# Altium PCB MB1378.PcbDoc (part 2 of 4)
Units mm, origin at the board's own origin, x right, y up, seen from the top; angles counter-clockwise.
Board outline 54.22 x 80.1 mm, 4 copper layers (Top Layer, L2-GND, L3, Bottom Layer), stack 0.771 mm thick; 206 components, 159 nets, 727 pads, 330 vias.
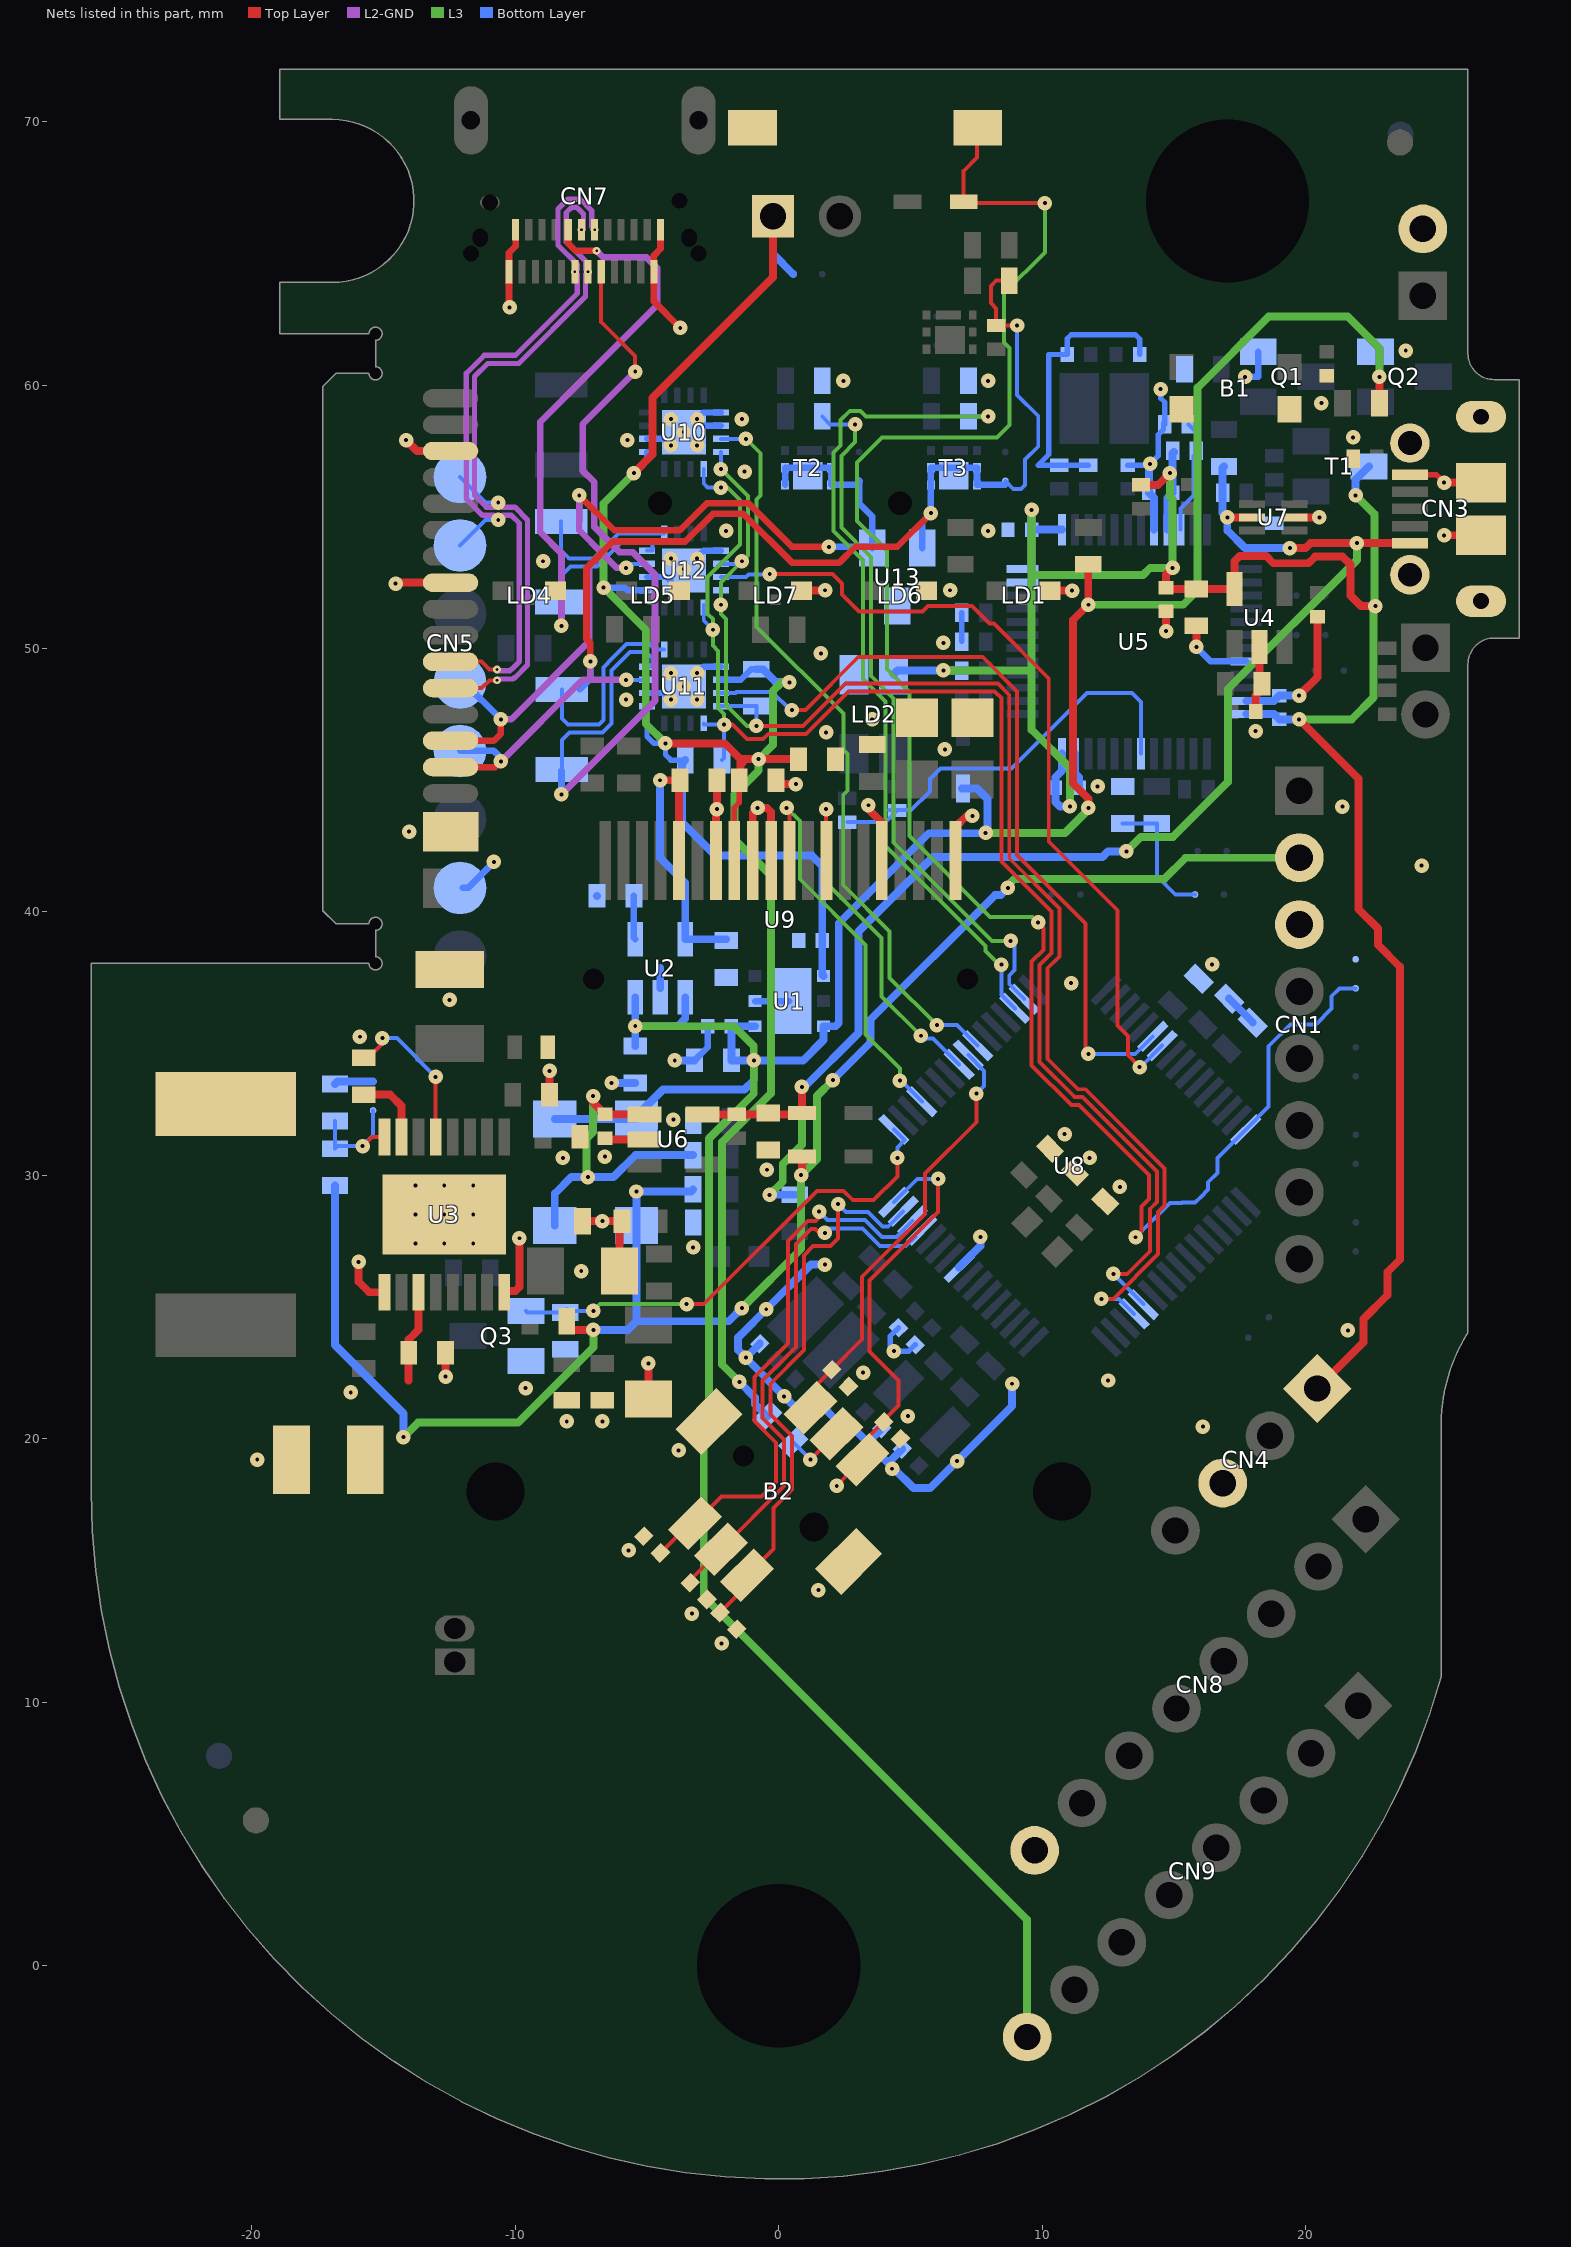
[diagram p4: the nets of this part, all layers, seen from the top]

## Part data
B1: library part MCD-01510, "Microminiature SMT Top, 2N, N.O., IP67", Manufacturer=C&K, Manufacturer_Part_Number="KMR721NG LFS", Package=KMR7
B2: library part MCD-00132, "Joystick, 4 dir, 1 OK", Manufacturer="XIEJIA Electronics", Manufacturer_Part_Number=MT-008A
C1 C3 C5 C11 C34 C35 C37 C38: library part MCD-00010, "Capacitor, MLCC, 1uF, 16V, X5R, 10%, 0603, T=0,8mm", Manufacturer=YAGEO, Manufacturer_Part_Number=CC0603KRX5R7BB105, Package=C0603
C2 C4 C44 C45 C46 C50 C51 C52 C53 C54: library part MCD-00102, "Capacitor, MLCC, 100nF, 16V, X7R, 10%, 0402, T=0,5mm", Manufacturer=YAGEO, Manufacturer_Part_Number=CC0402KRX7R7BB104, Package=C0402
C6 C49: library part MCD-01007, "Capacitor, MLCC, 10nF, 16V, X7R, 10%, 0603, T=0.8mm", Manufacturer=YAGEO, Manufacturer_Part_Number=CC0603KRX7R7BB103, Package=C0603
C7: library part MCD-00551, "Capacitor, MLCC, 2.2uF, 10V, X5R, 10%, 0603, T=0,8mm", Alternate_Manufacturer=YAGEO, Alternate_Manufacturer_Part_Number=CC0603KRX5R6BB225, Manufacturer=KEMET, Manufacturer_Part_Number=C0603C225K8PACTU, Package=C0603
C8 C9: library part MCD-01050, "Capacitor, X7R, 68nF, 50V, 10%, 0603, T=1mm", Manufacturer=AVX, Manufacturer_Part_Number=06035C683KAT2A, Package=C0603
C10 C18: library part MCD-01048, "Capacitor, NP0, 47pF, 50V, C0G, 5%, 1206, T=1.25mm", Manufacturer=AVX, Manufacturer_Part_Number=06035A470JAT4A, Package=C1206_H1P25
C12: library part MCD-00614, "Capacitor, MLCC, 22uF, 16V, 1210, X7R, 20%, T=2,5mm, ESR 2mohm@410KHz", Manufacturer=MURATA, Manufacturer_Part_Number=GCM32ER71C226ME19, Package=C1210
C13: library part MCD-01056, "Capacitor, X7R, 10µF, 50V, 20%, 1210, T=2.5mm", Manufacturer=TDK, Manufacturer_Part_Number=C3225X7R1H106M250AC, Package=C1210
C14: library part MCD-01053, "Capacitor, C-series, X5R, 1µF, 50V, 10%, 0603, T=0.8mm", Manufacturer=TDK, Manufacturer_Part_Number=C1608X5R1H105K080AB, Package=C0603
C15: library part MCD-01052, "Capacitor, X7R, 33nF, 50V, 5%, 0603, T=1.25mm", Manufacturer=AVX, Manufacturer_Part_Number=06035C333JAT2A, Package=C0603
C16: library part MCD-00009, "Capacitor, MLCC, 4.7uF, 16V, X5R, 10%, 0603, T=0.8mm", Manufacturer=YAGEO, Manufacturer_Part_Number=CC0603KRX5R7BB475, Package=C0603
C17: library part MCD-01049, "Capacitor, MLCC, 4.7nF, 100V, X7R, 10%, 0603, T=1mm", Manufacturer=AVX, Manufacturer_Part_Number=06031C472K4T2A, Package=C0603
C19 C20: library part MCD-00015, "Capacitor, MLCC, 10pF, 50V, NPO, 5%, 0402, T=0,5mm", Manufacturer=YAGEO, Manufacturer_Part_Number=CC0402JRNPO9BN100, Package=C0402
C21 C23 C32 C48: library part MCD-00238, "Capacitor, MLCC, 1uF, 6V3, X5R, 10%, 0603, T=0,8mm", Manufacturer=YAGEO, Manufacturer_Part_Number=CC0603KRX5R5BB105, Package=C0603
C22 C24 C26 C28 C29 C30 C31 C33: library part MCD-00006, "Capacitor, MLCC, 100nF, 16V, X7R, 10%, 0402, T=0.5mm", Manufacturer=YAGEO, Manufacturer_Part_Number=CC0402KRX7R7BB104, Package=C0402
C25: library part MCD-00011, "Capacitor, MLCC, 10nF, 16V, X7R, 10%, 0402, T=0.5mm", Manufacturer=YAGEO, Manufacturer_Part_Number=CC0402KRX7R7BB103, Package=C0402
C27: library part MCD-00638, "Capacitor, MLCC, 20pF, 50V, NPO, 5%, 0603, T=0,8mm", Manufacturer=YAGEO, Manufacturer_Part_Number=CC0603JRNPO9BN200, Package=C0603
C36 C41: library part MCD-01043, "Capacitor, Tantalum, 4.7µF, 25V, 10%, 1206", Manufacturer=VISHAY, Manufacturer_Part_Number=293D475X9025A2TE3, Package=CPOL_TAJ-A_1206_H180
C39 C40: library part MCD-01374, "Capacitor, MLCC, 5.6pF, 50V, NPO, 5%, 0402, T=0,5mm", Manufacturer=YAGEO, Manufacturer_Part_Number=CC0402BRNPO9BN5R6, Package=C0402
C42 C43: library part MCD-00556, "Capacitor, MLCC, 3.9pF, 50V, NPO, +-0.25pF, 0402, T=0,5mm", Manufacturer=YAGEO, Manufacturer_Part_Number=CC0402CRNPO9BN3R9, Package=C0402
C47: library part MCD-00097, "Capacitor, MLCC, 4.7uF, 16V, X5R, 20%, 0603, T=0,8mm", Manufacturer=MURATA, Manufacturer_Part_Number=GRM188R61C475MAAJ, Package=C0603
CC1 CC2 D+ D- GND SBU1 SBU2 VBUS: library part MCD-00177, "Test Point 2mm", Manufacturer=n/a
CN1: library part MCD-01382, "Header, 8x1, 2.54mm, RA, through-hole", Manufacturer=SAMTECH, Manufacturer_Part_Number=TSW_108_08_G_S_RA
CN2 JP1: library part MCD-00032, "Header, 2x1, 2,54mm, VR, TH, Height 5.84mm/2.54mm", Manufacturer=SAMTEC, Manufacturer_Part_Number=TSW-102-07-x-S
CN3: library part MCD-00028, "USB-MICRO-B, 0.65mm, RA, SMT, Bottom Mount,", Manufacturer=MOLEX, Manufacturer_Part_Number=1050170001
CN4: library part MCD-00029, "Header, 4x1, 2,54mm, VR, TH, Height 5.84mm/2.54mm", Manufacturer=SAMTEC, Manufacturer_Part_Number=TSW-104-07-x-S
CN5: library part MCD-01383, "Connector, USB TYpe-C Plug cable interface to PCB with specific layout", Manufacturer="ADVANCED-CONNECTEK (KSN) INC.", Manufacturer_Part_Number="TBD (custom-made connector)", Package="USB Type-C Pug captive cable"
CN6: library part MCD-00314, "Header, 2x1, 2.54mm, VR, TH, Height 6mm/3mm", Manufacturer=JIUBABA, Manufacturer_Part_Number=PHFS25-11-02-G0B115-T-1
CN7: library part MCD-01022, "USB Type-C connector DX07 Series RECEPTACLE", Manufacturer=JAE, Manufacturer_Part_Number=DX07S024JJ2, Package="2x24 pin"
CN8 CN9: library part MCD-00239, "Header, 8x1, 2,54mm, VR, TH, Height 5.84mm/2.54mm", Manufacturer=SAMTEC, Manufacturer_Part_Number=TSW-108-07-x-S
D1 D2: library part MCD-01059, "LOW DROP POWER SCHOTTKY RECTIFIER 1A 30V VF=0.3V", Manufacturer=STMICROELECTRONICS, Manufacturer_Part_Number=STPS1L30A, Package=DIO_SMA_1A_2K
D3 D4 D5 D6: library part MCD-00034, "BAT60JFILM", Manufacturer=STMICROELECTRONICS
HW1: library part MCD-00628, "\"ROHS\" logo footprint for PCB"
HW2: library part MCD-00627, "\"Hand\" ESD logo footprint for PCB"
HW4: library part MCD-00625, "\"STMicroelectronics\" logo footprint for PCB"
JP2: library part MCD-01428, "Header, 2x1, 1,27mm, Right Angled, Single Row, Height 3.05mm/1.27mm", Manufacturer="W & P Products", Manufacturer_Part_Number=707-2-02-2-20-00
L1: library part MCD-01372, "Inductor 6.8µH +/-20% Isat= 13.5A DCR=33.40 mOhm", Manufacturer="WURTH ELEKTRONIK", Manufacturer_Part_Number="744 373 580 68", Package=WE-LHMI_SMD_8040
L2: library part MCD-00552, "Bead,600R,350mA,0603", Manufacturer=TAI-TECH, Manufacturer_Part_Number=FCM1608KF-601T03
LD1 LD6 LD7: library part MCD-01376, "LED GREEN, 2.2V, 20mA, side", Manufacturer="BROADCOM LIMITED", Manufacturer_Part_Number=HSMG-C120, Package=HSM-C120
LD2: library part MCD-00051, "LED Bicolor", Alternate_Manufacturer=EVERLUCK, Alternate_Manufacturer_Part_Number=LE-RGW35280, Manufacturer="AVAGO TECHNOLOGIES", Manufacturer_Part_Number=HSMF-A201-A00J1
LD3: library part MCD-00587, "LED Red, 0603 SMD, 2V Forward Voltage", Alternate_Manufacturer="OSRAM OPTO SEMICONDUCTORS", Alternate_Manufacturer_Part_Number="LS Q976-NR-1", Manufacturer=VISHAY, Manufacturer_Part_Number=VLMS1300-GS08, Package="LED 0603"
LD4 LD5: library part MCD-01378, "LED ORANGE, 1.9V, 20mA, side", Manufacturer="BROADCOM LIMITED", Manufacturer_Part_Number=HSML-C120
Q1 Q2: library part MCD-01385, "Transistor Bipolar NPN, 45V, 500mA, 100MHz, 300mW, SOT23-3", Manufacturer="ON SEMICONDUCTOR", Manufacturer_Part_Number=BC817-25LT3G, Package=SOT23-3
Q3: library part MCD-01518, "MOSFET, Single N-Channel , Vgs(th): 2.5V, Id: 280mA, Vds(max): 60V, Vgs(max): +/-20V, Rdson:3 ohm@Vgs=5V", Alternate_Manufacturer=FAIRCHILD, Alternate_Manufacturer_Part_Number=NDS7002A, Manufacturer="ON SEMICONDUCTOR", Package=SOT23-3L
R1 R2 R8: library part MCD-00220, "Resistor,10K,0603,1%,1/10W", Manufacturer=YAGEO, Manufacturer_Part_Number=RC0603FR-0710KL, Package=R0603
R3 R32 R33 R52 R61: library part MCD-00354, "Resistor,470R,0603,1%,1/10W", Manufacturer=YAGEO, Manufacturer_Part_Number=RC0603FR-07470RL, Package=R0603
R4 R5 R7: library part MCD-00341, "Resistor,15K,0603,1%,1/10W", Manufacturer=YAGEO, Manufacturer_Part_Number=RC0603FR-0715KL, Package=R0603
R6: library part MCD-00426, "Resistor,2M,0603,1%,1/10W", Manufacturer=YAGEO, Manufacturer_Part_Number=RC0603FR-072ML, Package=R0603
R9: library part MCD-00478, "Resistor,43K,0603,1%,1/10W", Manufacturer=YAGEO, Manufacturer_Part_Number=RC0603FR-0743KL, Package=R0603
R10: library part MCD-01032, "Resistor 499K 1% 75V 0.063W", Manufacturer=MULTICOMP, Manufacturer_Part_Number=MC0603SAF4993T5E, Package=R0603
R11 R20 R21: library part MCD-00065, "Resistor,4K7,0402,1%,1/16W", Alternate_Manufacturer=YAGEO, Alternate_Manufacturer_Part_Number=RT0402FRE074K7L, Manufacturer_Part_Number=RC0402FR-074K7L, Package=R0402
R12: library part MCD-00055, "Resistor,2K7,0402,1%,1/16W", Manufacturer=YAGEO, Manufacturer_Part_Number=RC0402FR-072K7L, Package=R0402
R13 R22 R23: library part MCD-00052, "Resistor,0R,0402,5%,1/16W", Manufacturer=YAGEO, Manufacturer_Part_Number=RC0402JR-070RL, Package=R0402
R14 R17 R34: library part MCD-00059, "Resistor,100K,0402,1%,1/16W", Alternate_Manufacturer=YAGEO, Alternate_Manufacturer_Part_Number=RT0402FRE07100KL, Manufacturer_Part_Number=RC0402FR-07100KL, Package=R0402
R15 R16 R28 R30: library part MCD-00053, "Resistor,10K,0402,1%,1/16W", Manufacturer=YAGEO, Manufacturer_Part_Number=RC0402FR-0710KL, Package=R0402
R18 R45: library part MCD-00224, "Resistor,100R,0603,1%,1/10W", Manufacturer=YAGEO, Manufacturer_Part_Number=RC0603FR-07100RL, Package=R0603
R19 R25: library part MCD-00067, "Resistor,100R,0402,1%,1/16W", Manufacturer=YAGEO, Manufacturer_Part_Number=RC0402FR-07100RL, Package=R0402
R24 R26: library part MCD-00062, "Resistor,330R,0402,1%,1/16W", Manufacturer=YAGEO, Manufacturer_Part_Number=RC0402FR-07330RL, Package=R0402
R27: library part MCD-00069, "Resistor,36K,0402,1%,1/16W", Manufacturer=YAGEO, Manufacturer_Part_Number=RC0402FR-0736KL, Package=R0402
R29: library part MCD-00068, "Resistor,1K5,0402,1%,1/16W", Manufacturer=YAGEO, Manufacturer_Part_Number=RC0402FR-071K5L, Package=R0402
R31: library part MCD-00508, "Resistor,680R,0603,1%,1/10W", Manufacturer=YAGEO, Manufacturer_Part_Number=RC0603FR-07680RL, Package=R0603
R35 R36 R38 R39 R41 R44 R57 R58 R62: library part MCD-00056, "Resistor,0R,0603,5%,1/10W", Manufacturer=YAGEO, Manufacturer_Part_Number=RC0603JR-070RL, Package=R0603
R37 R42 R51 R59 R60: library part MCD-00223, "Resistor,100K,0603,1%,1/10W", Manufacturer=YAGEO, Manufacturer_Part_Number=RC0603FR-07100KL, Package=R0603
R40: library part MCD-00506, "Resistor,620K,0603,1%,1/10W", Manufacturer=YAGEO, Manufacturer_Part_Number=RC0603FR-07620KL, Package=R0603
R43 R54: library part MCD-00430, "Resistor,22K,0603,1%,1/10W", Manufacturer=YAGEO, Manufacturer_Part_Number=RC0603FR-0722KL, Package=R0603
R46 R47: library part MCD-00070, "Resistor,1K,0603,1%,1/10W", Manufacturer=YAGEO, Manufacturer_Part_Number=RC0603FR-071KL, Package=R0603
R48 R49 R50: library part MCD-01029, "0.015 Ohm 1W 1% 1206 Shunt resistor for current sensing", Manufacturer=PANASONIC, Manufacturer_Part_Number=ERJ8CWFR015V, Package=1206
R53: library part MCD-00259, "Resistor,33K,0603,1%,1/10W", Manufacturer=YAGEO, Manufacturer_Part_Number=RC0603FR-0733KL, Package=R0603
R55: library part MCD-00257, "Resistor,1M,0603,1%,1/10W", Manufacturer=YAGEO, Manufacturer_Part_Number=RC0603FR-071ML, Package=R0603
R56: library part MCD-00333, "Resistor,5K1,0402,1%,1/16W", Manufacturer=YAGEO, Manufacturer_Part_Number=RC0402FR-075K1L, Package=R0402
R63: library part MCD-00222, "Resistor,47K,0603,1%,1/10W", Manufacturer=YAGEO, Manufacturer_Part_Number=RC0603FR-0747KL, Package=R0603
SB1 SB2 SB3 SB4 SB5 SB6 SB9: library part MCD-00071, "Solder Bridge ON"
SB7 SB8 SB10 SB11 SB12 SB13 SB14 SB15: library part MCD-00072, "Solder Bridge OFF"
SB16: library part MCD-00072, "Solder Bridge OFF", Manufacturer=YAGEO, Manufacturer_Part_Number=RC0603JR-070RL, Package=SB0603
SW1: library part MCD-01373, "Reed switch, CT05 series, SPST-NO, CMS, 500mA, 140Vdc, 5W", Manufacturer="COTO TECHNOLOGY", Manufacturer_Part_Number=CT05-G1, Package=CT05
T1: library part MCD-00073, "NPN Bipolar Transistor", Manufacturer=NXP, Manufacturer_Part_Number=BSR14
T2 T3 T5: library part MCD-01028, "N-channel 20 V, 0.025 O typ., 6 A STripFET™ V Power MOSFET in a PowerFLAT™ 2x2 package", Manufacturer=STMICROELECTRONICS, Manufacturer_Part_Number=STL6N2VH5, Package="PowerFLAT 2x2"
TARGET1 TARGET2 TARGET3 TARGET4: library part MIRE, "MIRE"
U1: library part MCD-00215, "Low quiescent current and low noise voltage regulators", Manufacturer=STMICROELECTRONICS, Manufacturer_Part_Number=LD39050PU33R
U2: library part MCD-01030, "LDO VOLTAGE REGULATOR, 3.6V, 150mA, 5-SOT-23, FULL REEL", Manufacturer="TEXAS INSTRUMENTS", Package=REG_SOT23-5L
U3: library part MCD-01016, "Integrated Circuit 40V, 1A Synchronous Buck-Boost DC/DC Converter with Programmable Output Current", Manufacturer="LINEAR TECHNOLOGY", Manufacturer_Part_Number=LTC3114-1, Package="16-Lead Plastic TSSOP + exposed pad"
U4: library part MCD-00086, "Ultra low drop-low noise BiCMOS voltage, regulators low ESR capacitors compatible", Manufacturer=STMICROELECTRONICS, Manufacturer_Part_Number=LD3985M33R
U5: library part MCD-00085, "Medium-density performance line ARM-based 32-bit MCU with 128KB Flash", Manufacturer=STMICROELECTRONICS, Manufacturer_Part_Number=STM32F103CBT6
U6: library part MCD-00083, "Enhanced single channel power switches with active low enable pin", Alternate_Manufacturer="TEXAS INSTRUMENTS", Alternate_Manufacturer_Part_Number=TPS2041C, Manufacturer=STMICROELECTRONICS
U7: library part MCD-00169, "USB OTG FS ESD protection", Manufacturer=STMICROELECTRONICS, Manufacturer_Part_Number=USBLC6-2P6
U8: library part MCD-01047, "ARM® Cortex®-M0+ 32-bit MCU, 128 KB Flash, 32 KB RAM, / 4x USART, timers, ADC, DAC, comm. I/F, 1.65-3.6V", Manufacturer=STMICROELECTRONICS, Manufacturer_Part_Number=STM32G071RBT6, Package=LQFP64
U9: library part MCD-01511, "128*64 20-pin OLED display driver SSD1306BZ Parallel or SPI interface", Manufacturer=RITDISPLAY, Manufacturer_Part_Number=9OL9935701000
U10 U11 U12: library part MCD-01017, "Texas Intruments High- or Low-Side Measurement, Bidirectional CURRENT/POWER MONITOR with I2C™ Interface", Manufacturer=TI, Manufacturer_Part_Number=INA230, Package=QFN16
U13: library part MCD-01027, "DUAL TRANSIL ARRAY FOR ESD PROTECTION", Manufacturer=STMICROELECTRONICS, Manufacturer_Part_Number=ESDA25L, Package=ESD_SOT23
U14: library part MCD-01207, "High power Transient voltage suppressor:25V/35A EOS and ESD transients protection.", Manufacturer=STMICROELECTRONICS, Manufacturer_Part_Number=ESDA25P35-1U1M, Package=QFN1610
X1 X3: library part MCD-00092, "Crystal 8Mhz, 8pF, -+50PPM, SMD", Manufacturer=NDK, Manufacturer_Part_Number="NX3225GD 8MHz EXS00A-CG04874"
X2: library part MCD-00091, "Crystal 32.768kHz, 6pF, -+20PPM, R=50K, SMD", Manufacturer=NDK, Manufacturer_Part_Number="NX3215SA 32.768KHz EXS00A-MU00525"

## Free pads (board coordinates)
  round 0.508 on Mech16: 1(79.747,-56.535) 1(85.97,-56.535)
  round 0.8 hole 2.2 unplated mask+0.8: H1(-10.756,17.999) H1(10.756,17.999)
  round 0.8 hole 6.2 unplated mask+2.8: H1(0,0) H1(17.035,66.99)
  round 0.5 hole 0.9 unplated: H2(-4.509,55.512) H2(4.603,55.512)

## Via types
v1: diameter 0.55, hole 0.15, Top Layer to Bottom Layer, 308 vias
v2: diameter 0.3, hole 0.1, Top Layer to L2-GND, 22 vias

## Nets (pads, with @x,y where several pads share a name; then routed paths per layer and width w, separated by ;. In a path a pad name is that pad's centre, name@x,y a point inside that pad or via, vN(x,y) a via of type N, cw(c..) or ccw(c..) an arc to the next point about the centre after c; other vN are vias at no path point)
3V3_LDO: C3.1 C4.2 C37.1 CN6.1 R45.1 R46.2 R47.2 SB6.1 U1.4 U9.8 U10.9 U11.2 U11.9 U12.9 | length 88.1
  Top Layer w0.2: U9.8@-1.687,41.949 -1.687,43.963 -1.5,44.15 C37.1@-1.5,45
  Top Layer w0.3: v1(-5.497,56.662) -4.797,57.362 -4.797,59.512 -0.217,64.092 CN6.1@-0.217,66.412 ; v1(-4.3,46.4) -2.051,46.4 -1.45,45.799 ; C37.1@-1.5,45 -1.45,45.05 -1.45,45.6 ; C3.1@0.75,45.799 v1(-0.761,45.799) -1.251,45.799 ; -1.45,45.6 -1.251,45.799 ; -1.45,45.6 -1.45,45.799 ; -1.45,45.799 -1.251,45.799
  L3 w0.3: v1@-5.522,56.637 -6.647,55.512 v1(-6.647,52.312) -5.047,50.712 -5.047,47.147 v1(-4.3,46.4) ; v1(-1.497,22.162) -2.147,22.812 -2.147,31.262 -0.297,33.112 -0.297,41.384 -1.675,42.761 -1.675,44.451 -0.761,45.365 v1(-0.761,45.799) -0.222,46.337 -0.222,48.387 0.103,48.712 v1(0.403,48.712)
  Bottom Layer w0.2: U11.9@-4.997,47.812 -4.997,46.664 -4.733,46.4 v1(-4.3,46.4) -4.3,45.967 -4.096,45.762 R46.2@-3.547,45.762
  Bottom Layer w0.24: v1(-6.647,52.312) -5.847,52.312 -5.747,52.212 U12.9@-4.997,52.212 ; v1(-5.497,56.662) -4.997,57.162 U10.9@-4.997,57.462 ; U11.2@-2.197,48.812 -1.447,48.812 -1.047,49.212 R47.2@-0.847,49.212
  Bottom Layer w0.3: R46.2@-3.547,45.762 -3.675,45.635 -3.675,43.41 -2.403,42.137 1.263,42.137 1.653,41.747 C4.2@1.653,38.912 1.653,37.612 U1.4@1.703,37.562 ; v1(-1.497,22.162) -0.897,21.562 -0.897,21.312 R45.1@-0.437,20.852 ; R47.2@-0.847,49.212 -0.597,49.212 -0.117,48.732 0.383,48.732 v1(0.403,48.712) ; CN6.1@-0.217,66.412 -0.217,64.982 SB6.1@0.553,64.212
3V3_STLK: C23.2 C24.2 C28.2 C29.2 C30.2 C31.2 CN4.1 LD2.4 R13.2 R17.2 R20.1 T1.3 U4.5 U5.1 U5.9 U5.24 U5.36 U5.48 | length 91.9
  Top Layer w0.3: R17.2@13.753,56.212 14.403,56.212 v1(14.853,56.662) ; v1(14.953,53.062) 14.703,52.812 C24.2@14.703,52.312 14.703,52.262 C23.2@15.853,52.262 U4.5@17.303,52.262 17.303,53.312 17.503,53.512 18.503,53.512 18.778,53.237 20.114,53.237 20.364,53.487 21.402,53.487 21.703,53.187 21.703,52.012 22.103,51.612 v1(22.653,51.612) ; v1(19.753,47.312) 22.003,45.062 22.003,40.112 22.745,39.37 22.745,38.755 23.578,37.922 23.578,26.801 23.103,26.326 23.103,25.449 22.203,24.549 22.203,23.662 CN4.1@20.447,21.906
  L3 w0.3: v1@6.143,49.172 v1(6.253,49.172) 9.603,49.172 ; v1(9.603,55.262) 9.603,52.787 ; v1(11.055,44.005) 11.055,45.46 9.603,46.912 9.603,49.172 ; v1(14.853,56.662) 14.853,55.762 14.953,55.662 v1(14.953,53.062) 14.103,53.062 13.828,52.787 9.603,52.787 ; v1(19.753,47.312) 21.753,47.312 22.578,48.137 22.578,51.537 v1(22.653,51.612) 22.613,51.652 22.613,55.102 v1(21.903,55.812) ; 9.603,49.172 9.603,52.787
  Bottom Layer w0.3: LD2.4@4.353,49.012 4.513,49.172 v1(6.253,49.172) R13.2@6.943,49.172 ; U5.48@9.603,53.062 C28.2@9.603,54.512 ; v1(9.603,55.262) C28.2@9.603,54.512 ; U5.36@10.753,46.012 10.753,45.362 10.503,45.112 C31.2@10.503,44.712 10.503,44.177 10.675,44.005 v1(11.055,44.005) ; U5.1@10.753,54.512 C28.2@9.603,54.512 ; U5.9@14.753,54.512 14.753,55.712 C29.2@14.953,55.912 14.953,57.412 R20.1@15.003,57.462 ; U5.24@17.753,47.512 18.803,47.512 C30.2@19.003,47.312 v1(19.753,47.312) ; v1(21.903,55.812) 21.903,56.412 T1.3@22.403,56.912
3V6_LDO: C7.2 C38.1 U2.5 U9.5 | length 12
  Top Layer w0.3: v1(-4.5,45) C38.1@-3.787,45 ; U9.5@-3.787,41.749 U9.5@-3.787,41.949 C38.1@-3.787,45 ; C38.1@-3.75,45 C38.1@-3.787,45
  Bottom Layer w0.3: v1(-4.5,45) -4.5,42.05 -3.547,41.097 U2.5@-3.547,38.962 C7.2@-1.997,38.962
5V: C1.2 C2.2 C5.1 CN9.8 D1.2 D2.2 D4.1 R3.2 R51.2 U1.1 U1.6 U2.1 U2.3 | length 119.2
  Top Layer w0.3: R3.2@11.75,53.2 11.75,51.665 v1(11.753,51.662) 11.178,51.087 11.178,44.874 11.755,44.297 v1(11.755,43.95) v1@11.755,43.85 ; R51.2@22.803,59.312 v1(22.803,60.312)
  L3 w0.3: v1(-5.447,35.662) -1.697,35.662 -0.947,34.912 v1(-0.947,34.362) -0.947,33.099 -2.647,31.399 -2.647,20.966 -2.847,20.766 -2.847,14.012 9.418,1.747 CN9.8@9.418,-2.71 ; v1(7.85,43) 10.863,43 11.755,43.892 v1(11.755,43.95) ; v1(11.753,51.662) 15.353,51.662 15.903,52.212 15.903,59.903 18.6,62.6 21.6,62.6 22.803,61.397 v1(22.803,60.312)
  Bottom Layer w0.3: D1.2@-8.503,32.132 D2.2@-5.403,32.132 -5.403,32.257 -4.397,33.262 -1.297,33.262 -0.947,33.612 v1(-0.947,34.362) ; C5.1@-5.447,34.912 v1(-5.447,35.662) ; U2.3@-5.447,36.762 v1(-5.447,35.662) ; U2.1@-3.547,36.762 -3.547,35.953 -3.838,35.662 v1(-5.447,35.662) ; U1.1@-0.897,35.662 C2.2@-1.797,35.662 C1.2@-1.797,34.362 v1(-0.947,34.362) ; D4.1@6.953,44.692 7.523,44.692 7.925,44.29 7.925,43.075 v1(7.85,43) 7.837,42.987 5.697,42.987 2.278,39.568 2.278,35.787 2.153,35.662 U1.6@1.703,35.662 1.703,35.136 0.929,34.362 v1(-0.947,34.362)
5V_SMPS_VBUS: C11.2 C12.2 CN1.2 D2.1 D6.1 R2.2 R6.2 R53.2 U3.3 | length 70.4
  Top Layer w0.3: -14.047,22.212 -14.047,23.762 -13.672,24.137 U3.3@-13.672,25.562 ; R6.2@-8.047,24.462 -8.047,24.135 v1(-7.035,24.135) ; v1(0.853,30.012) 0.883,30.042 D6.1@0.883,30.712
  L3 w0.3: v1(-14.247,20.062) -13.697,20.612 -9.897,20.612 -7.035,23.475 v1(-7.035,24.135) ; v1(-1.397,24.962) 0.853,27.212 v1(0.853,30.012) 1.453,30.612 1.453,33.012 v1(2.053,33.612) ; v1(8.703,40.912) 8.703,41.012 8.939,41.249 14.639,41.249 15.449,42.059 CN1.2@19.763,42.059
  Bottom Layer w0.3: R53.2@-16.847,29.612 -16.847,23.562 -14.247,20.962 v1(-14.247,20.062) ; v1(-7.035,24.135) -5.725,24.135 -5.397,24.462 ; R2.2@-3.253,29.467 -3.333,29.387 v1(-5.403,29.387) D2.1@-5.403,28.102 -5.403,24.468 -5.397,24.462 ; v1(-1.397,24.962) -1.897,24.462 -4.147,24.462 -5.397,24.462 ; v1(2.053,33.612) 3.478,35.037 3.478,35.908 8.207,40.637 8.428,40.637 v1(8.703,40.912)
5V_STLK: C33.2 D1.1 R1.2 U6.1 | length 12.6
  Top Layer w0.3: v1(-7.047,33.012) -7.047,32.762 C33.2@-6.597,32.312 U6.1@-5.097,32.312
  L3 w0.3: v1@-7.297,29.937 -7.297,31.4 -7.047,31.65 v1(-7.047,33.012)
  Bottom Layer w0.3: D1.1@-8.503,28.102 -8.503,29.307 -7.872,29.937 v1(-7.247,29.937) -6.272,29.937 -5.442,30.767 R1.2@-3.253,30.767
5V_USB_CHGR: C32.2 CN3.1 D5.1 R28.1 R30.2 R31.1 R42.1 U6.5 U7.5 | length 55.5
  Top Layer w0.3: U6.5@-2.897,32.312 0.833,32.312 D5.1@0.883,32.362 v1(0.883,33.362) ; v1(17.028,54.976) U7.5@17.973,54.976 ; v1(19.403,53.812) 20.003,53.812 20.19,54 v1(21.95,54) 22.601,54 22.603,53.999 ; 22.589,53.999 22.603,53.999 ; CN3.1@23.963,53.999 22.603,53.999
  L3 w0.3: v1(-0.347,29.262) 0.153,29.762 0.153,30.432 0.883,31.162 v1(0.883,33.362) ; v1(13.2,42.3) 13.75,42.85 14.967,42.85 17.05,44.933 17.05,48.46 21.95,53.36 v1(21.95,54)
  Bottom Layer w0.3: v1(-0.347,29.262) -0.397,29.262 R31.1@0.603,29.262 ; v1(0.883,33.362) 0.989,33.362 3.028,35.401 3.028,39.257 5.858,42.087 12.291,42.087 12.503,42.3 v1(13.2,42.3) ; R42.1@16.903,56.912 16.853,56.862 R28.1@16.853,55.912 16.853,55.151 v1(17.028,54.976) 17.028,54.487 17.703,53.812 v1(19.403,53.812)
AIN_1: R20.2 R21.2 U5.10 | length 4.4
  Bottom Layer w0.15: U5.10@15.253,54.512 15.253,55.312 15.753,55.812 15.753,57.312 15.903,57.462 15.903,58.162 R21.2@15.553,58.512
ALERT_CC1: U8.38 U11.3 | length 30.5
  Top Layer w0.15: v1(0.503,47.662) 1.008,47.662 3.018,49.672 7.744,49.672 9.05,48.367 9.05,42.164 11.653,39.561 11.653,34.712 v1(11.753,34.612)
  Bottom Layer w0.15: U11.3@-2.197,48.312 -1.642,48.312 -1.597,48.357 -0.254,48.357 0.441,47.662 v1(0.503,47.662) ; v1(11.753,34.612) 13.535,34.612 U8.38@14.199,35.277
ALERT_CC2: U8.39 U12.3 | length 31.9
  Top Layer w0.15: v1(-0.341,52.826) 2.039,52.826 2.403,52.462 2.403,52.05 3.053,51.4 5.46,51.4 5.673,51.612 7.34,51.612 8.003,50.95 8.164,50.95 10.25,48.864 10.25,42.666 12.853,40.064 12.853,35.692 13.253,35.292 13.253,34.562 v1(13.703,34.112)
  Bottom Layer w0.15: U12.3@-2.197,52.712 -1.247,52.712 -1.147,52.812 -0.354,52.812 v1(-0.341,52.826) ; v1(13.703,34.112) 13.742,34.112 U8.39@14.553,34.923
ALERT_VBUS: U8.26 U10.3 | length 28.3
  L3 w0.15: v1(-1.247,57.962) -0.697,57.412 -0.697,55.805 -0.841,55.662 -0.841,50.825 2.453,47.532 2.453,46.3 2.453,46.145 2.606,45.991 2.606,44.6 2.45,44.444 2.45,41.015 4.203,39.262 4.203,37.497 v1(6,35.7)
  Bottom Layer w0.15: U10.3@-2.197,57.962 v1(-1.247,57.962) ; v1(6,35.7) 6.776,35.7 U8.26@7.552,34.923
CC1_N: CN7.A5 R49.1 U11.12 | length 32.7
  Top Layer w0.152: CN7.A5@-6.74,64.299 -6.74,62.405 -5.447,61.112 v1(-5.447,60.512)
  L2-GND w0.25: v1(-8.247,44.462) -4.697,48.012 -4.697,52.812 -5.547,53.662 -6.047,53.662 -6.997,54.612 -6.997,56.312 -7.447,56.762 -7.447,58.512 v1(-5.447,60.512)
  Bottom Layer w0.152: R49.1@-8.237,45.399 -8.237,46.523 -7.947,46.812 -6.697,46.812 -6.347,47.162 -6.347,48.954 -6.346,48.955 -6.346,49.164 -5.647,49.862 -5.047,49.862 -4.797,49.612 -4.797,49.312 U11.12@-4.997,49.312
  Bottom Layer w0.25: v1(-8.247,44.462) R49.1@-8.247,45.359
CC1_P: CC1.1 CN5.A5 R49.2 R55.2 R56.2 SB8.1 T3.1 T3.2 T3.5 T3.6 T3.8 U11.11 U11.13 U13.2 | length 56.6
  Top Layer w0.15: R56.2@8.253,62.262 8.253,62.912 8.053,63.112 8.053,63.762 8.253,63.962 R55.2@8.753,63.962
  Top Layer w0.152: R56.2@8.253,62.262 v1(9.053,62.262)
  Top Layer w0.25: CN5.A5@-12.457,45.499 -10.761,45.499 v1(-10.547,45.712) ; v1(-7.147,49.512) -7.147,50.209 -7.297,50.359 -7.297,53.062 -6.297,54.062 -3.547,54.062 -2.497,55.112 -1.347,55.112 0.503,53.262 2.303,53.262 2.903,53.862 4.503,53.862 v1(5.778,55.137)
  L2-GND w0.25: v1(-10.547,45.712) -7.447,48.812 -7.147,48.812 ; v1(-7.147,49.512) -7.147,48.812 ; v1(-5.797,48.812) -7.147,48.812
  Bottom Layer w0.15: SB8.1@8.603,56.362 8.903,56.062 9.203,56.062 9.353,56.212 ; v1(9.053,62.262) 9.053,59.62 9.853,58.82 9.853,57.671 9.351,57.17 9.351,56.214
  Bottom Layer w0.152: R49.2@-8.237,48.449 -8.237,47.352 -8.002,47.117 -6.824,47.117 -6.652,47.289 -6.652,49.289 -6.302,49.639 -5.774,50.167 -4.902,50.167 -4.697,49.962 U11.13@-4.347,49.962 ; v1(-5.797,48.812) U11.11@-4.997,48.812 ; 9.351,56.214 9.353,56.212
  Bottom Layer w0.25: CC1.1@-12.097,46.112 -10.814,46.112 -10.547,45.846 v1(-10.547,45.712) ; R49.2@-7.547,48.462 -7.147,48.862 v1(-7.147,49.512) ; U13.2@5.453,53.812 5.453,54.812 v1(5.778,55.137) T3.1@5.778,56.212 T3.2@5.778,56.862 T3.5@7.528,56.862 T3.6@7.528,56.212 8.603,56.212
CC2_N: CN7.B5 R50.1 U12.12 | length 26.4
  Top Layer w0.25: CN7.B5@-7.99,65.899 -7.99,65.374 -7.715,65.099 v2(-6.915,65.099)
  L2-GND w0.25: v1(-8.247,50.862) -8.247,53.612 -9.047,54.412 -9.047,58.612 -4.615,63.045 -4.615,64.449 -5.015,64.849 -6.665,64.849 v2(-6.915,65.099)
  Bottom Layer w0.152: R50.1@-8.262,51.774 -8.247,51.759 -8.247,52.762 -7.897,53.112 -6.897,53.112 -5.947,54.062 -4.935,54.062 -4.797,53.925 -4.797,53.712 U12.12@-4.997,53.712
  Bottom Layer w0.25: v1(-8.247,50.862) R50.1@-8.247,51.759
CC2_P: CC2.1 CN5.B5 R50.2 SB7.1 T2.1 T2.2 T2.5 T2.6 T2.8 U12.11 U12.13 U13.1 | length 43.4
  Top Layer w0.25: CN5.B5@-12.457,46.499 -10.811,46.499 -10.547,46.762 v1(-10.547,47.312) ; v1(-7.572,55.812) -6.246,54.486 -3.752,54.486 -2.726,55.512 -1.147,55.512 0.503,53.862 v1(1.903,53.862)
  L2-GND w0.25: v1(-10.547,47.312) -10.147,47.312 -7.197,50.262 -7.197,53.112 -6.697,53.612 ; v1(-7.572,55.812) -7.572,54.487 -6.697,53.612 ; v1(-5.797,53.062) -6.147,53.062 -6.697,53.612
  Bottom Layer w0.152: CC2.1@-11.997,48.712 CC2.1@-11.947,48.712 ; R50.2@-8.262,54.824 -8.262,53.727 -7.952,53.417 -7.024,53.417 -6.074,54.367 U12.13@-4.347,54.367 ; v1(-5.797,53.062) -5.647,53.212 U12.11@-4.997,53.212 ; U13.1@3.503,53.862 U13.1@3.553,53.812
  Bottom Layer w0.25: CC2.1@-11.947,48.712 v1(-10.547,47.312) ; R50.2@-7.572,54.837 v1(-7.572,55.812) ; T2.1@0.24,56.212 T2.2@0.24,56.862 T2.5@1.99,56.862 T2.6@1.99,56.212 3.015,56.212 ; v1(1.903,53.862) U13.1@3.503,53.862 ; SB7.1@3.053,56.362 3.053,55.512 3.553,55.012 U13.1@3.553,53.812
CS_DISP: U8.20 U9.11 | length 15.4
  Top Layer w0.15: v1(0.3,43.95) 0.413,43.837 U9.11@0.413,41.949
  L3 w0.15: v1(0.3,43.95) 0.8,43.45 0.8,41.241 3.3,38.741 3.3,35.35 4.6,34.05 v1(4.6,33.6)
  Bottom Layer w0.15: v1(4.6,33.6) 4.6,33.633 U8.20@5.431,32.802
D1_N: CN5.A7 CN7.A7 CN7.B7 D-.1 | length 28.7
  Top Layer w0.152: CN5.A7@-12.407,49.499 -11.281,49.499 -10.986,49.204 v2(-10.697,49.204)
  L2-GND w0.202: v2(-10.697,49.204) -10.648,49.155 -10.216,49.155 -10.17,49.2 -10.152,49.2 -9.847,49.505 -9.847,54.756 -10.147,55.056 -10.473,55.056 v1(-10.647,54.882) -10.821,55.056 -11.241,55.056 -11.859,55.674 -11.859,60.45 -11.177,61.133 -10,61.133 -7.646,63.488 -7.646,64.205 v2(-7.74,64.299) -7.646,64.393 -7.646,64.58 -8.377,65.311 -8.377,66.678 -7.994,67.061 -7.536,67.061 -7.103,66.628 -7.103,66.012 v2(-6.99,65.899)
  Bottom Layer w0.152: D-.1@-12.097,53.912 -11.127,54.882 v1(-10.647,54.882)
D1_P: CN5.A6 CN7.A6 CN7.B6 D+.1 | length 28.2
  Top Layer w0.152: CN5.A6@-12.407,48.499 -11.281,48.499 -10.986,48.794 v2(-10.697,48.794)
  L2-GND w0.202: v2(-10.697,48.794) -10.648,48.843 -10.086,48.843 -10.041,48.888 -10.023,48.888 -9.535,49.375 -9.535,54.886 -10.018,55.368 -10.473,55.368 v1(-10.647,55.542) -10.821,55.368 -11.097,55.368 -11.547,55.818 -11.547,60.321 -11.048,60.821 -9.871,60.821 -7.334,63.359 -7.334,64.205 v2(-7.24,64.299) -7.334,64.393 -7.334,64.709 -8.065,65.44 -8.065,66.549 -7.865,66.749 -7.665,66.749 -7.415,66.499 -7.415,65.974 v2(-7.49,65.899)
  Bottom Layer w0.152: D+.1@-12.097,56.512 -11.127,55.542 v1(-10.647,55.542)
D/C_DISP: U8.24 U9.13 | length 14.3
  Top Layer w0.15: v1(1.8,43.9) 1.8,41.962 U9.13@1.813,41.949 U9.13@1.813,41.749
  L3 w0.15: v1(1.8,43.9) 1.8,41.115 3.903,39.012 3.903,36.797 v1(5.4,35.3)
  Bottom Layer w0.15: v1@5.29,35.3 v1(5.4,35.3) 5.5,35.2 5.861,35.2 U8.24@6.845,34.216
DOOR_SENSE: D3.2 SB16.2 SW1.2 U8.48 | length 71.9
  Top Layer w0.15: SW1.2@7.528,69.762 7.528,68.637 7.023,68.132 D3.2@7.023,66.962 7.073,66.912 v1(10.103,66.912) ; v1(9.85,39.6) 10.053,39.397 10.053,38.561 9.603,38.111 9.603,34.178 11.112,32.669 11.402,32.669 14.053,30.018 14.053,29.107 13.763,28.818 13.763,27.863 v1(13.55,27.65)
  L3 w0.15: v1@9.69,39.6 v1(9.85,39.6) 9.638,39.812 8.025,39.812 4.96,42.878 4.96,48.356 4.103,49.214 4.103,53.714 2.978,54.839 2.978,57.063 3.927,58.012 8.284,58.012 8.753,58.481 8.753,61.412 8.553,61.612 8.553,63.488 10.103,65.038 v1(10.103,66.912)
  Bottom Layer w0.15: v1(13.55,27.65) 14.85,28.95 15.3,28.95 15.312,28.962 15.803,28.962 16.003,29.162 16.01,29.162 16.303,29.455 16.303,29.738 16.653,30.088 16.653,30.659 U8.48@17.735,31.741 18.6,32.607 18.6,34.902 19.433,35.735 20.39,35.735 20.99,36.335 20.99,36.8 21.29,37.1 SB16.2@21.9,37.1
EN_SMPS: Q3.1 R63.2 U8.17 | length 18.4
  Top Layer w0.15: v1(-3.497,25.112) -2.847,25.112 1.453,29.412 2.46,29.412 2.81,29.062 3.603,29.062 4.503,29.962 v1(4.503,30.662)
  L3 w0.15: v1(-7.04,24.855) -6.783,25.112 v1(-3.497,25.112)
  Bottom Layer w0.15: Q3.1@-9.6,24.85 -9.55,24.8 R63.2@-8.1,24.8 ; R63.2@-8.045,24.855 v1(-7.04,24.855) ; U8.17@4.37,31.741 4.776,31.336 4.503,31.062 v1@4.503,30.873
  Bottom Layer w0.25: R63.2@-8.1,24.8 R63.2@-8.045,24.855
ENCC1: R58.2 U8.30 | length 31.9
  L3 w0.15: v1(7.953,58.812) 3.31,58.812 3.11,59.012 2.695,59.012 2.353,58.67 2.353,57.711 2.078,57.436 2.078,54.467 3.203,53.342 3.203,48.841 4.06,47.984 4.06,42.505 7.853,38.712 7.853,38.512 8.365,38 v1(8.45,38)
  Bottom Layer w0.15: R58.2@7.203,58.812 v1(7.953,58.812) ; v1(8.45,38) 8.45,36.854 U8.30@8.967,36.337
ENCC2: R57.2 U8.31 | length 26.9
  L3 w0.15: v1(2.903,58.512) 2.903,57.837 2.378,57.312 2.378,54.591 3.503,53.466 3.503,48.965 4.36,48.108 4.36,42.629 8.089,38.9 v1(8.8,38.9)
  Bottom Layer w0.15: R57.2@1.653,58.812 1.953,58.512 v1(2.903,58.512) ; v1(8.8,38.9) 8.95,38.75 8.95,37.793 8.75,37.593 8.75,37.261 U8.31@9.32,36.691
GND: B1.2 B1.4 B2.7 B2.8 C1.1 C2.1 C3.2 C4.1 C5.2 C6.1 C7.1 C10.1 C11.1 C12.1 C13.1 C14.1 C15.1 C16.1 C17.1 C18.1 C19.2 C20.2 C21.2 C22.1 C23.1 C24.1 C25.1 C26.1 C27.1 C28.1 C29.1 C30.1 C31.1 C32.1 C33.1 C36.2 C37.2 C38.2 C39.2 C40.2 C41.2 C42.2 C43.2 C44.1 C45.1 C46.1 C47.1 C48.1 C49.1 C50.1 C51.1 C52.1 C53.1 C54.1 CN1.3 CN3.5 CN3.6 CN3.7 CN3.8 CN3.9 CN3.10 CN3.11 CN4.3 CN5.A1 CN5.A12 CN5.B1 CN7.A1 CN7.A12 CN7.B1 CN7.B12 CN8.8 GND.1 JP1.2 LD1.2 LD2.1 LD4.2 LD5.2 LD6.2 LD7.2 Q1.2 Q2.2 Q3.2 R4.1 R5.1 R9.1 R10.1 R11.1 R14.1 R15.2 R16.1 R21.1 R27.1 R34.1 R35.1 R37.1 R38.1 R40.1 R43.1 R54.1 R59.1 R60.1 R63.1 SB9.2 SB16.1 SW1.1 U1.2 U1.EP U2.2 U3.1 U3.8 U3.17 U4.2 U5.8 U5.20 U5.23 U5.35 U5.47 U6.2 U7.2 U8.9 U9.7 U9.9 U9.10 U9.16 U9.20 U10.1 U10.2 U10.10 U10.17 U11.1 U11.10 U11.17 U12.1 U12.10 U12.17 U13.3 U14.2 | length 119.7
  Top Layer w0.2: CN3.5@23.963,56.599 24.963,56.599 v1(25.263,56.299)
  Top Layer w0.25: v1@-10.24,62.974 CN7.A12@-10.24,64.299 -10.24,65.024 -9.99,65.274 CN7.B1@-9.99,65.899 ; CN7.B12@-4.49,65.899 -4.49,65.174 -4.74,64.924 CN7.A1@-4.74,64.299 -4.74,63.174 v1(-3.738,62.172)
  Top Layer w0.3: v1(-15.947,26.712) -15.947,25.962 -15.547,25.562 U3.1@-14.972,25.562 ; v1(-14.547,52.462) -14.511,52.499 CN5.B1@-12.457,52.499 ; v1(-14.147,57.912) -13.734,57.499 CN5.A1@-12.457,57.499 ; v1(-12.647,22.362) C11.1@-12.647,23.262 ; U3.8@-10.372,25.612 -9.997,25.612 -9.847,25.762 v1(-9.847,27.612) ; v1@-10.24,62.974 v1(-10.215,62.949) ; C14.1@-8.697,33.062 v1(-8.697,33.962) ; R10.1@-7.447,28.262 v1(-6.697,28.262) C17.1@-5.947,28.262 -6.047,28.162 C10.1@-6.047,26.362 ; C33.1@-6.547,31.362 U6.2@-5.097,31.362 ; C18.1@-4.947,21.512 v1(-4.947,22.862) ; U9.7@-2.387,41.749 U9.7@-2.387,41.949 v1@-2.387,43.9 ; v1(-2.35,43.9) C38.2@-2.35,45 ; U9.9@-0.987,41.749 U9.9@-0.987,41.949 -0.987,43.763 v1(-0.8,43.95) -0.45,43.95 -0.287,43.787 U9.10@-0.287,41.949 U9.10@-0.287,41.749 ; C37.2@-0.1,45 0.05,44.85 v1(0.65,44.85) ; LD7.2@0.863,52.199 1.75,52.199 v1(1.764,52.212) ; v1(3.4,44.05) 3.4,43.911 3.913,43.398 U9.16@3.913,41.949 U9.16@3.913,41.749 ; U9.20@6.713,41.749 U9.20@6.713,41.949 6.713,43.223 7.14,43.65 v1(7.35,43.65) ; LD1.2@10.293,52.199 v1(11.139,52.199) ; v1(14.703,50.662) C24.1@14.703,51.412 ; v1(15.853,50.062) C23.1@15.853,50.862 ; C22.1@18.103,47.612 18.103,48.212 18.353,48.462 C21.2@18.353,48.662 18.353,48.862 18.253,48.962 U4.2@18.253,50.062 ; U7.2@19.583,54.976 v1(20.528,54.976) ; v1(19.753,48.212) 20.453,48.912 C25.1@20.453,51.212 ; v1(25.263,54.299) CN3.10@26.663,54.299 ; v1(25.263,56.299) CN3.11@26.663,56.299
  Bottom Layer w0.2: C46.1@4.547,24.211 4.229,23.892 4.229,23.468 v1(4.37,23.327) 4.936,23.327 C45.1@5.184,23.574 ; R11.1@6.953,50.262 R14.1@6.953,51.362 ; R16.1@11.753,56.962 R15.2@10.653,56.962 9.853,56.962 10.253,57.362 10.253,61.162 C20.2@10.953,61.162 10.953,61.762 11.103,61.912 13.538,61.912 13.703,61.747 C19.2@13.703,61.162 ; C26.1@13.253,56.962 14.053,56.962 14.403,57.312 14.403,58.112 14.603,58.312 R21.1@14.603,58.562 ; v1(14.5,59.85) 14.5,59.5 14.653,59.347 R21.1@14.653,58.512
  Bottom Layer w0.24: U11.10@-4.997,48.312 -4.347,48.312 v1(-4.097,48.062) ; U12.10@-4.997,52.712 -4.247,52.712 U12.17@-4.097,52.562 ; U10.10@-4.997,57.962 -4.347,57.962 v1(-4.097,57.712) ; v1(-3.097,49.062) -2.847,49.312 U11.1@-2.197,49.312 ; U12.17@-3.097,53.462 -2.847,53.712 U12.1@-2.197,53.712 ; U10.2@-2.197,58.462 -2.847,58.462 v1(-3.097,58.712) -2.847,58.962 U10.1@-2.197,58.962
  Bottom Layer w0.25: GND.1@-11.997,40.912 -11.797,40.912 v1(-10.811,41.899) ; C1.1@-3.197,34.362 -2.697,34.862 C2.1@-2.697,35.662 ; U1.2@-0.897,36.612 U1.EP@0.403,36.612 ; v1(15.853,50.062) 16.403,49.512 U5.20@17.753,49.512 ; v1(17.703,60.312) 18.203,60.312 Q1.2@18.203,61.262
  Bottom Layer w0.3: R54.1@-16.847,33.462 -16.747,33.562 SB9.2@-15.397,33.562 ; v1(-6.347,33.512) C5.2@-5.447,33.512 ; U2.2@-4.497,37.112 -4.497,37.878 ; v1(-3.947,34.362) C1.1@-3.197,34.362 ; C43.2@-0.721,23.61 v1(-1.251,23.079) ; v1(1.753,26.612) 1.221,26.612 v1(-0.473,24.918) -1.428,23.963 -1.548,23.842 -1.548,23.377 v1(-1.251,23.079) ; C40.2@3.911,20.392 3.38,19.862 ; C39.2@4.689,19.614 v1@4.158,19.084 ; U8.9@6.845,26.509 7.653,27.316 v1(7.653,27.662) ; v1(8.861,22.089) 8.861,21.241 v1(6.775,19.155) 5.749,18.129 5.113,18.129 4.341,18.901 v1@4.158,19.084 ; U5.35@11.253,46.012 11.253,45.262 11.403,45.112 C31.1@11.403,44.712 ; v1@14.053,56.962 C29.1@14.053,55.912 14.253,55.712 U5.8@14.253,54.512 ; R38.1@17.098,36.707 17.995,35.81 R37.1@17.995,35.795 ; U5.23@17.753,48.012 18.803,48.012 C30.1@19.003,48.212 v1(19.753,48.212) ; v1(-1.251,23.079) v1(0.204,21.612) 0.402,21.413 0.552,21.263 0.893,21.263 C42.2@1.259,21.63 1.863,21.025 2.497,20.392 2.85,20.392 3.38,19.862 ; 3.38,19.862 v1@4.158,19.084
  other v1: -2.166,12.231 -3.297,13.362 1.506,14.259 -5.702,15.767 4.303,18.862 -19.797,19.212 -3.797,19.562 16.103,20.462 -8.047,20.662 -6.697,20.662 4.902,20.863 -16.247,21.762 -9.605,21.92 12.503,22.212 3.203,22.512 21.603,24.112 -7.497,26.362 -3.247,27.262 -13.797,27.412 -12.697,27.412 -11.597,27.412 -13.797,28.512 -12.697,28.512 -11.597,28.512 12.953,29.562 -13.797,29.612 -12.697,29.612 -11.597,29.612 -0.447,30.212 -8.197,30.662 11.803,30.662 -6.597,30.712 10.853,31.562 -3.997,32.112 -15.897,35.262 -12.497,36.662 11.1,37.3 16.453,38.012 24.403,41.762 -14.034,43.049 21.4,44 12.103,44.762 6.305,46.17 1.803,46.812 18.103,46.862 3.545,47.31 -5.797,48.062 -3.097,48.062 -3.597,48.562 -4.097,49.062 1.603,49.812 6.253,50.212 6.503,52.212 -3.597,53.012 -8.947,53.312 -4.097,53.412 -3.097,53.412 -1.997,54.462 7.953,54.462 -1.297,56.712 14.103,57.012 -3.097,57.712 -5.747,57.912 21.803,58.012 -3.597,58.212 -4.097,58.712 -1.397,58.712 20.603,59.312 2.453,60.162 7.953,60.162 23.803,61.312
I2C1_SCL: R46.1 U8.60 U10.5 U11.5 U12.5 | length 53.8
  Top Layer w0.15: v1(-2.071,47.112) -1.747,47.112 -1.197,46.562 -0.597,46.562 -0.397,46.762 1.042,46.762 2.651,48.371 8.197,48.371 8.45,48.118 8.45,41.915 10.353,40.012 10.353,38.437 9.903,37.987 9.903,34.302 11.236,32.969 11.526,32.969 14.353,30.142 14.353,28.983 14.103,28.733 14.103,27.134 13.231,26.262 v1(12.703,26.262)
  L3 w0.15: v1(-2.197,56.112) -1.947,56.112 -1.472,55.637 -1.472,53.945 -2.697,52.72 -2.697,51.312 -2.497,51.112 v1(-2.497,50.712) -2.497,50.112 -2.297,49.912 -2.297,47.738 -2.071,47.512 v1(-2.071,47.112)
  Bottom Layer w0.15: U11.5@-2.847,47.162 -2.847,47.112 v1(-2.071,47.112) -2.071,45.839 R46.1@-2.147,45.762 ; U12.5@-2.847,51.662 U12.5@-2.847,51.562 -2.847,51.062 v1(-2.497,50.712) ; U10.5@-2.847,56.812 -2.847,56.262 -2.697,56.112 v1(-2.197,56.112) ; v1(12.703,26.262) U8.60@13.846,25.119
I2C1_SDA: R47.1 U8.61 U10.4 U11.4 U12.2 U12.4 | length 54.6
  Top Layer w0.15: v1(-0.847,47.062) 0.918,47.062 2.527,48.671 8.321,48.671 8.75,48.242 8.75,42.039 10.653,40.137 10.653,38.312 10.203,37.862 10.203,34.427 11.361,33.269 11.65,33.269 14.653,30.267 14.653,28.858 14.403,28.608 14.403,27.009 12.706,25.312 v1(12.253,25.312)
  L3 w0.15: v1(-2.197,56.812) -2.19,56.812 -1.172,55.795 -1.172,53.537 v1(-1.397,53.312) -2.197,52.512 v1(-2.197,51.662) -2.197,51.312 -1.997,51.112 -1.997,47.862 -1.197,47.062 v1(-0.847,47.062)
  Bottom Layer w0.15: U11.4@-2.197,47.812 R47.1@-0.847,47.812 v1(-0.847,47.062) ; v1(-2.197,51.662) U12.4@-2.197,52.212 ; U12.2@-2.197,53.212 -1.497,53.212 v1(-1.397,53.312) ; v1(-2.197,56.812) U10.4@-2.197,57.462 ; v1(12.253,25.312) 12.921,25.312 U8.61@13.492,24.741
JOY_DOWN: B2.3 C52.2 U8.15 | length 21.5
  Top Layer w0.15: C52.2@-2.228,13.404 -1.202,14.43 B2.3@-1.202,14.817 -0.197,15.821 -0.197,17.377 0.503,18.077 0.503,20.097 -0.321,20.921 -0.321,22.089 0.953,23.362 0.953,26.962 1.303,27.312 1.96,27.312 2.253,27.605 v1(2.253,28.912)
  Bottom Layer w0.15: v1(2.253,28.912) 2.553,28.612 3.391,28.612 3.941,28.062 4.156,28.062 U8.15@4.724,28.63
JOY_LEFT: B2.1 C51.2 U8.14 | length 21.5
  Top Layer w0.15: C51.2@-4.492,15.667 -3.362,16.797 B2.1@-3.182,16.797 -2.166,17.812 -0.647,17.812 -0.097,18.362 -0.097,19.849 -0.921,20.672 -0.921,22.337 0.353,23.611 0.353,27.512 1.103,28.262 1.403,28.262 1.533,28.393 v1(1.533,28.626)
  Bottom Layer w0.15: v1(1.533,28.626) 1.847,28.312 3.267,28.312 3.917,27.662 4.463,27.662 U8.14@5.078,28.276
JOY_RIGHT: B2.6 C53.2 U8.16 | length 15.5
  Top Layer w0.15: v1(2.203,18.212) 2.203,18.221 B2.6@3.182,19.201 ; B2.6@3.182,19.837 C53.2@3.982,20.637 3.982,20.687 4.553,21.257 4.553,22.212 3.453,23.312 3.453,26.012 6.053,28.612 v1(6.053,29.862)
  Bottom Layer w0.15: U8.16@4.37,28.984 4.379,28.984 5.258,29.862 v1@6.003,29.862
JOY_SEL: B2.2 C50.2 U8.13 | length 20.5
  Top Layer w0.15: C50.2@-3.36,14.536 -3.36,14.639 B2.2@-2.192,15.807 0.203,18.201 0.203,19.973 -0.621,20.797 -0.621,22.213 0.653,23.487 0.653,27.388 1.227,27.962 1.403,27.962 1.553,27.812 v1(1.753,27.812)
  Bottom Layer w0.15: v1(1.753,27.812) 1.917,27.976 3.178,27.976 3.842,27.312 4.303,27.312 ; 4.309,27.312 4.821,27.312 U8.13@5.195,27.687
JOY_UP: B2.4 C54.2 U8.25 | length 16.4
  Top Layer w0.15: B2.4@1.202,21.181 1.202,21.817 C54.2@2.002,22.617 ; C54.2@2.008,22.617 3.153,23.762 3.153,26.137 5.545,28.53 5.545,30.062 7.5,32.017 v1(7.5,33.1)
  Bottom Layer w0.15: U8.25@7.199,34.57 7.8,33.969 7.8,33.4 v1(7.5,33.1)
LED_STLINK: R24.2 R26.2 U5.30 | length 15.8
  Bottom Layer w0.15: R24.2@2.603,43.412 4.062,43.412 R26.2@4.5,43.85 ; R26.2@4.203,43.862 5.028,43.862 5.742,44.577 5.742,45.052 6.138,45.447 8.838,45.447 11.703,48.312 13.403,48.312 13.753,47.962 U5.30@13.753,46.012
MCO: C27.2 R18.2 SB5.2 | length 5
  Bottom Layer w0.15: C27.2@13.053,43.362 R18.2@14.353,43.362 14.353,41.362 15.053,40.662 SB5.2@15.803,40.662
MODE: R53.1 R54.2 SB9.1 U3.16 | length 4.6
  Top Layer w0.15: v1(-15.797,31.112) -15.447,31.462 U3.16@-14.972,31.462
  Bottom Layer w0.15: R54.2@-16.847,32.062 R53.1@-16.847,31.012 -16.747,31.112 v1(-15.797,31.112) -15.397,31.512 SB9.1@-15.397,32.462
NetB2_5: B2.5 R45.2 | length 2.3
  Top Layer w0.15: v1(1.203,19.212) 1.214,19.212 B2.5@2.192,20.191
  Bottom Layer w0.15: R45.2@0.553,19.862 v1(1.203,19.212)
NetC6_2: C6.2 U2.4 | length 1.7
  Bottom Layer w0.25: C6.2@-5.497,40.612 -5.497,39.012 U2.4@-5.447,38.962
NetC8_1: C8.1 U3.13 | length 5.9
  Top Layer w0.15: C8.1@-15.597,34.462 -15.047,35.012 v1(-15.047,35.212) ; U3.13@-13.022,31.462 v1(-13.022,33.737)
  Bottom Layer w0.15: v1(-15.047,35.212) -14.497,35.212 v1(-13.022,33.737)
NetC8_2: C8.2 L1.1 U3.15 | length 2.8
  Top Layer w0.3: C8.2@-15.747,33.062 -14.747,33.062 -14.322,32.637 U3.15@-14.322,31.462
